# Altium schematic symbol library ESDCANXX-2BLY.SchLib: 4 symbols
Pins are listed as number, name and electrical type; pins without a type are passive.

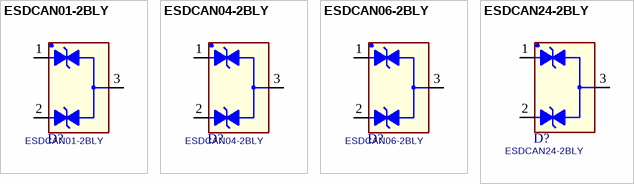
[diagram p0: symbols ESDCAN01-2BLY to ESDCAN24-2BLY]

## ESDCAN01-2BLY
designator D?
footprint ST_SOT23-3L
pins: 1 K1, 2 K2, 3 A

## ESDCAN04-2BLY
designator D?
footprint ST_SOT23-3L
pins: 1 K1, 2 K2, 3 A

## ESDCAN06-2BLY
designator D?
footprint ST_SOT23-3L
pins: 1 K1, 2 K2, 3 A

## ESDCAN24-2BLY
designator D?
footprint ST_SOT23-3L
pins: 1 K1, 2 K2, 3 A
